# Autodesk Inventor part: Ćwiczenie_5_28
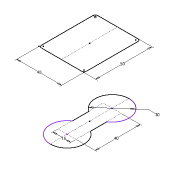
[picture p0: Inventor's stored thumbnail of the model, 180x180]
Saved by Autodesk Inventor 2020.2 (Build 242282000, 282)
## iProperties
Created: 2005-04
Part Number: Ćwiczenie_5_28
Document SubType Name: Modeling
Designer: F.Stasiak
Manufacturer: Standard
Standards Organization: Custom
Density: 1 g/cm^3
Material: Ogólny
Appearance: Domyślna
Manager: www.cadconsulting.pl
Company: Fabian Stasiak CAD Consulting
Author: F.Stasiak
Subject: Zbiór ćwiczeń. Autodesk Inventor 2020. Kurs podstawowy
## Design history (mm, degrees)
sketch "Szkic1"
  geometry: L1 (-8, 20)-(8, 20); L2 (8, 20)-(8, -20); L3 (8, -20)-(-8, -20); L4 (-8, -20)-(-8, 20); L5 (0, 20)-(0, -20); L6 (-8, 7.311)-(-8, -7.441); L7 (8, 7.282)-(8, -7.311); L8 (0, 35)-(0, -35); A1 r 15 centre (0, 20) between (0, 35) and (-8, 7.311); A2 r 15 centre (0, -20) between (0, -35) and (8, -7.311); A3 r 14.941 centre (0, -20.059) between (-8, -7.441) and (0, -35); A4 r 15.013 centre (0, 19.987) between (8, 7.282) and (0, 35); 2 further points
  constraints: 16 end point, 8 point on circle, 4 centre point, 4 parallel, 4 point on line, 3 coincident, 3 midpoint, 2 tangent, 1 collinear, 1 equal radius, 1 horizontal, 1 perpendicular
  dimensions: "d0" = 40 distance between parallel lines of L3 L1; "d1" = 30 diameter of A1; "d3" = 16 distance of L2.end L3.end
node "Płaszczyzna konstrukcyjna1"
sketch "Szkic2"
  geometry: L1 (-18, 25)-(18, 25); L2 (20, 23)-(20, -23); L3 (18, -25)-(-18, -25); L4 (-20, -23)-(-20, 23); L5 (0, 25)-(0, -25); A1 r 2 centre (-18, 23) between (-18, 25) and (-20, 23); A2 r 2 centre (18, 23) between (20, 23) and (18, 25); A3 r 2 centre (18, -23) between (18, -25) and (20, -23); A4 r 2 centre (-18, -23) between (-20, -23) and (-18, -25); 4 further points
  constraints: 10 end point, 8 point on circle, 8 tangent, 4 centre point, 4 point on line, 3 equal radius, 3 midpoint, 2 parallel, 1 coincident, 1 horizontal, 1 perpendicular
  dimensions: "d5" = 50 distance between parallel lines of L3 L1; "d6" = 40 distance of point (20, -25) point (-20, -25); "d7" = 2 radius of A1
node "Korpusy bryłowe"
node "Korpusy powierzchniowe"
